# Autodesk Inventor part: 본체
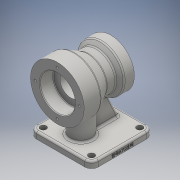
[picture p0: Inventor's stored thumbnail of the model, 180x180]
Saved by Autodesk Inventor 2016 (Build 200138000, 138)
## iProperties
Created: 2019-01
Part Number: 본체
Material: 일반
Document SubType Name: Modeling
Designer: 2-PC07
Density: 1 g/cm^3
Appearance: 기본값
Author: 2-PC07
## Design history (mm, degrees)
sketch "스케치1"
  geometry: L1 (-46, -46)-(46, -46); L2 (46, -46)-(46, 46); L3 (46, 46)-(-46, 46); L4 (-46, 46)-(-46, -46); L5 (-46, -46)-(46, 46); L6 (46, -46)-(-46, 46); 1 further point
  constraints: 12 end point, 2 midpoint, 2 parallel, 1 horizontal, 1 perpendicular
  dimensions: "d0" = 92 distance of L2.end L3.end; "d1" = 92 distance between parallel lines of L3 L1
extrude "돌출1" new body sketch "스케치1" distance "d2" = 10; taper "d3" = 0 deg
sketch "스케치2"
  geometry: L1 (-46, -46)-(46, -46) reference; C1 r 16 at (0, -16); 1 further point
  constraints: 1 centre point, 1 vertical alignment
  dimensions: "d4" = 30 distance from line of C1.centre L1; "d5" = 32 diameter of C1
extrude "돌출2" join sketch "스케치2" distance "d6" = 70; taper "d7" = 0 deg
node "작업 평면1"
sketch "스케치3"
  geometry: L1 (-56.761, 80)-(55.188, 80); L2 (-46, 0)-(46, 0) reference; L3 (-51, 80)-(-51, 120); L4 (-51, 120)-(-26, 120); L5 (-26, 120)-(-5.215, 108); L6 (-5.215, 108)-(8.126, 108); L7 (8.126, 108)-(14, 115); L8 (14, 115)-(29, 115); L9 (29, 115)-(29, 80); L10 (-46, 0)-(-46, 10) reference; 1 further point
  constraints: 16 end point, 2 parallel, 2 perpendicular, 2 point on line, 1 horizontal, 1 vertical
  dimensions: "d9" = 80 distance between parallel lines of L2 L1; "d10" = 80 diameter of L4 L1; "d11" = 5 distance between parallel lines of L10 L3; "d12" = 70 diameter of L8 L1; "d13" = 56 diameter of L6 L1; "d14" = 150 deg angle of L6 L5; "d15" = 130 deg angle of L7 L6; "d16" = 80 distance between parallel lines of L9 L3; "d17" = 25 distance of L3.end L4.end; "d18" = 15 distance of L7.end L8.end
revolve "회전1" sketch "스케치3" stored, may be unused: angle "d19" = 90 deg
node "작업 평면2"
sketch "스케치4"
  geometry: L1 (36, 10)-(30.155, 22.535); L2 (-46, 10)-(46, 10) reference; L3 (46, 0)-(46, 10) reference; 2 further points
  constraints: 2 end point, 1 coincident, 1 point on line
  dimensions: "d21" = 25 deg angle of L1 L3; "d22" = 10 distance from line of L3 point (36, 10)
feature "리브1" sketch "스케치4" dims "d23" = 1, "d24" = 10, "d25" = 0, "d26" = 0, "d27" = 1, "d28" = 1
sketch "스케치5"
  geometry: C1 r 26 at (0, 0); C2 r 40 at (0, 0) reference; 1 further point
  constraints: 1 centre point, 1 concentric
  dimensions: "d29" = 52 diameter of C1
extrude "돌출3" cut sketch "스케치5" distance "d30" = 20; taper "d31" = 0 deg
sketch "스케치6"
  geometry: C1 r 20 at (0, 0); C2 r 35 at (0, 0) reference; 1 further point
  constraints: 1 centre point, 1 concentric
  dimensions: "d32" = 40 diameter of C1
extrude "돌출4" cut sketch "스케치6" distance "d33" = 17; taper "d34" = 0 deg
sketch "스케치7"
  geometry: C1 r 16 at (0, 0); A1 r 40 centre (0, 0) between (-12.49, 38) and (12.49, 38) reference; 1 further point
  constraints: 1 centre point, 1 concentric
  dimensions: "d35" = 32 diameter of C1
extrude "돌출5" cut sketch "스케치7" stored distance "d36" = 17; taper "d37" = 0 deg
sketch "스케치8" dims "d38" = 66
  geometry: C1 r 40 at (0, 0) reference; 3 further points
  constraints: 2 vertical alignment, 3 other
hole "구멍1" sketch "스케치8" at (0, 33) diameter "d39" = 3.242; stored, may be unused: countersink angle "d43" = 90 deg, drill point angle "d45" = 118 deg; dims "d40" = 9, "d41" = 4, "d42" = 2, "d44" = 11
sketch "스케치9" dims "d49" = 55
  geometry: A1 r 40 centre (0, 0) between (-12.49, 38) and (12.49, 38) reference; 3 further points
  constraints: 2 horizontal alignment, 3 other
hole "구멍2" sketch "스케치9" at (27.5, 0) diameter "d50" = 3.242; stored, may be unused: countersink angle "d54" = 90 deg, drill point angle "d56" = 118 deg; dims "d51" = 9, "d52" = 4, "d53" = 2, "d55" = 11
fillet "모깎기1" dims "d60" = 1, "d61" = 0.6
chamfer "모따기1" distance "d62" = 1; stored, may be unused: second distance "d63" = 2, angle "d64" = 45 deg
fillet "모깎기2" dims "d65" = 10
hole "구멍3" diameter "d68" = 9; stored, may be unused: countersink angle "d72" = 90 deg, drill point angle "d74" = 118 deg; dims "d69" = 9, "d70" = 4, "d71" = 2, "d73" = 11, "d81" = 10, "d82" = 10
fillet "모깎기3" dims "d83" = 3
fillet "모깎기4" dims "d84" = 3
fillet "모깎기5" dims "d85" = 3
sketch "스케치10"
  geometry: L1 (-7, 16)-(-7, 56); L2 (-7, 56)-(-1, 56); L3 (-1, 56)-(-1, 16); L4 (-1, 16)-(-7, 16); L5 (-7, 36)-(-1, 36); L6 (-4, 16)-(-4, 56); L7 (-7, -10)-(0, -10) reference; L8 (0, 0)-(0, 72) reference; 1 further point
  constraints: 4 end point, 4 midpoint, 2 other
  dimensions: "d86" = 6 distance between parallel lines of L3 L1; "d87" = 40 distance between parallel lines of L2 L4; "d88" = 46 distance between parallel lines of L7 L5; "d89" = 4 distance between parallel lines of L8 L6
feature "엠보싱1" sketch "스케치10" dims "d0" = 92, "d1" = 92, "d90" = 0.5, "d91" = 0
fillet "모깎기6" dims "d92" = 3
node "솔리드1"
pattern_circular "원형 패턴1" dims angle "d47" = 360 deg
pattern_circular "원형 패턴2" dims angle "d58" = 360 deg
pattern_linear "직사각형 패턴1" dims "d77" = 72, "d80" = 72
other parameters: "d8" = 0, "d20" = 0
